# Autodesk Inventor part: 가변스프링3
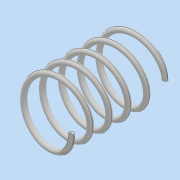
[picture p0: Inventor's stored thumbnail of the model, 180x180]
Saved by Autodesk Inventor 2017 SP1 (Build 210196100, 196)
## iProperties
Part Number: 가변스프링3
Material: 일반
Document SubType Name: Modeling
Designer: MRC
Density: 1 g/cm^3
Appearance: 기본값
Mass: 1.07302 g
Surface Area: 21.7217 cm^2
Volume: 1.07302 cm^3
Author: MRC
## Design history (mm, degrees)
sketch "스케치1"
  geometry: L1 (0, 0)-(0, 36.411); L2 (0, 0)-(11, 0); L3 (0, 36.411)-(11, 36.411); C1 r 1 at (11, 0)
  constraints: 6 end point, 2 horizontal, 1 centre point, 1 coincident, 1 vertical
  dimensions: "d0" = 36.4112 distance of L1.start L1.end (derived); "d1" = 2 diameter of C1; "d2" = 22 diameter of L2.end L1
feature "코일1" sketch "스케치1" pitch "d3" = 10; turns "d5" = 5; dims "d4" = 36.4112 (= d0), "d6" = 0, angle "d7" = 90 deg, angle "d8" = 90 deg, "d9" = 0, "d10" = 0
sketch "스케치2"
  geometry: L1 (15, 0)-(-15, 0); L2 (-15, 0)-(-15, 36.411); L3 (-15, 36.411)-(15, 36.411); L4 (15, 36.411)-(15, 0); 1 further point
  constraints: 8 end point, 2 parallel, 1 horizontal, 1 midpoint, 1 perpendicular
  dimensions: "d11" = 36.4112 distance of L3.end L1.start (= d0); "d12" = 30 distance between parallel lines of L2 L4; "d13" = 15 distance from line of point (0, 0) L4 (= 0.5 x d12)
extrude "돌출1" sketch "스케치2" stored distance "d14" = 30; taper "d15" = 0 deg
node "솔리드1"
